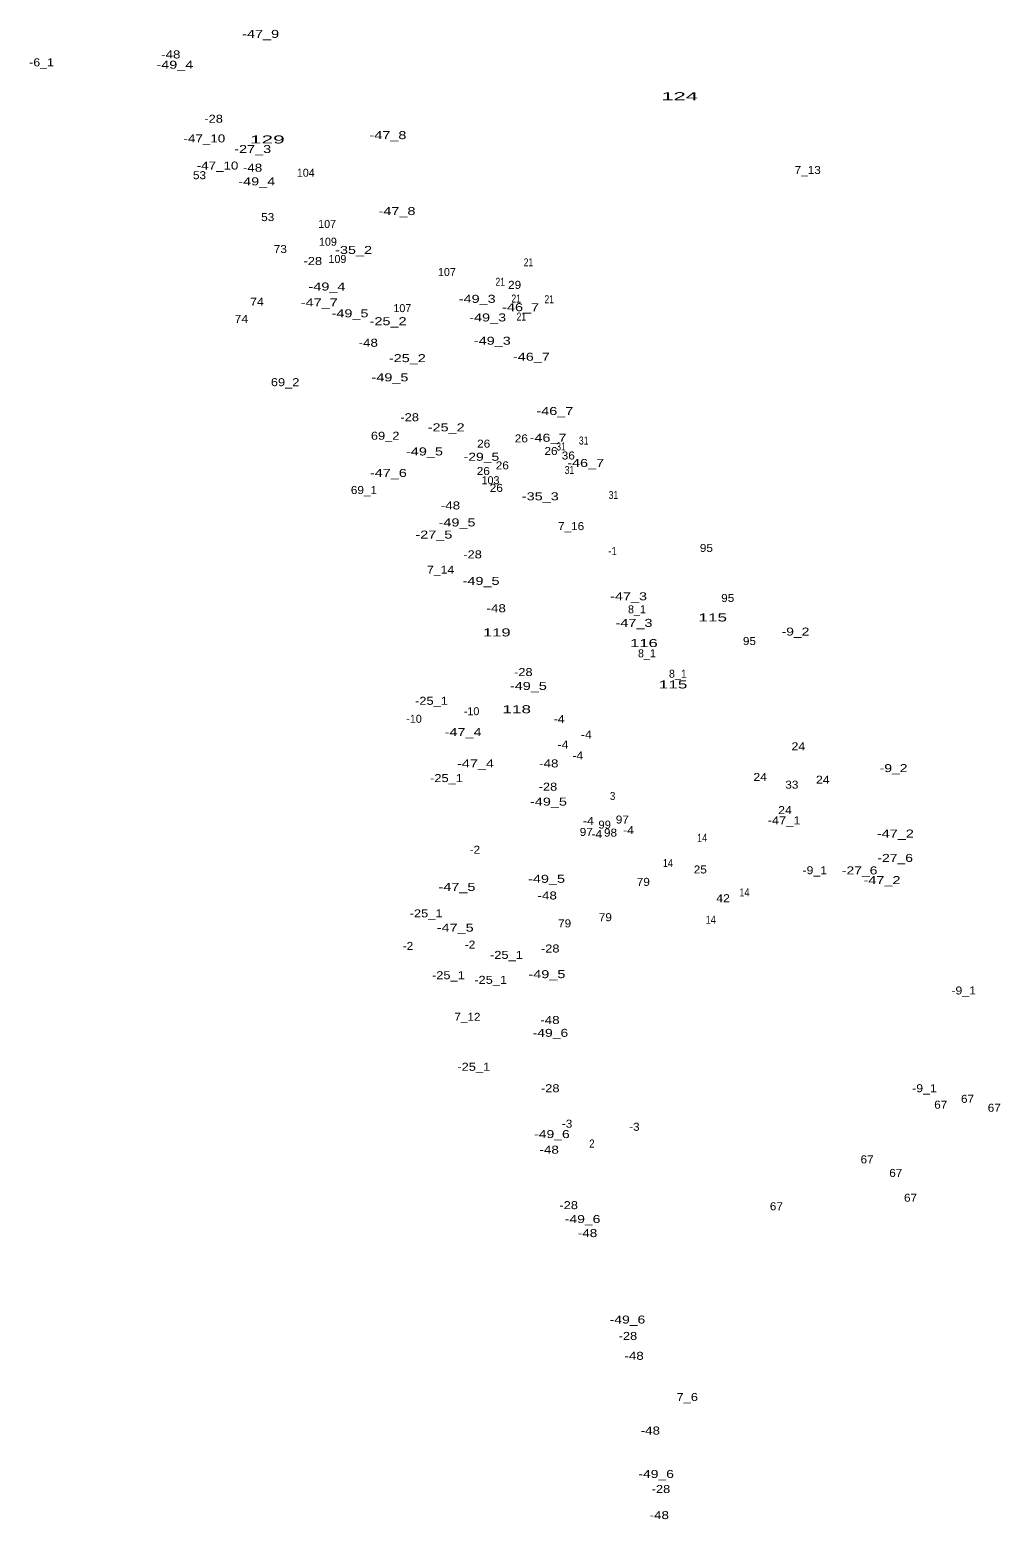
# Model space of a CAD drawing. Extents: x -663705 to -661666, y -1002081 to -999269.
# Drawn here: x -662976 to -662490, y -1002081 to -1001336 of the extents above; entities that cross this region are included whole.
import ezdxf
from ezdxf.enums import TextEntityAlignment as Align

# ---------------------------------------------------------------- set-up
doc = ezdxf.new("R2010")
doc.units = 0
doc.header["$LTSCALE"] = 1.6
doc.layers.add('24', color=7, linetype='Continuous')

msp = doc.modelspace()

# ---------------------------------------------------------------- texts
at = {"layer": '24'}
for s, width, p in [('-47_9', 1.35, (-662860.101, -1001340.27)), ('-6_1', 1.15, (-662969.66, -1001354.49)), ('-49_4', 1.35, (-662903.01, -1001355.68)), ('-48', 1.25, (-662905.05, -1001350.54)), ('124', 2.05, (-662650.563, -1001371.41)), ('-28', 1.2, (-662883.62, -1001382.68)), ('-47_10', 1.25, (-662888.24, -1001392.52)), ('129', 1.95, (-662856.773, -1001393.04)), ('-47_8', 1.35, (-662796.439, -1001390.88)), ('-27_3', 1.35, (-662864.07, -1001397.83)), ('-47_10', 1.25, (-662881.65, -1001406.1)), ('-48', 1.25, (-662864.14, -1001407.17)), ('7_13', 1.1, (-662586.549, -1001408.3)), ('53', 1.1, (-662890.679, -1001410.9)), ('-49_4', 1.35, (-662862.03, -1001414)), ('-47_8', 1.35, (-662791.91, -1001428.85)), ('53', 1.1, (-662856.559, -1001431.85)), ('73', 1.1, (-662850.26, -1001447.81)), ('-35_2', 1.35, (-662813.61, -1001448.28)), ('-28', 1.2, (-662834.02, -1001453.83)), ('21', 0.8, (-662726.179, -1001454.48)), ('-49_4', 1.35, (-662826.939, -1001466.56)), ('21', 0.8, (-662740.309, -1001464.19)), ('29', 1.1, (-662733.11, -1001465.73)), ('74', 1.15, (-662861.94, -1001474.19)), ('-47_7', 1.35, (-662830.791, -1001474.54)), ('-49_3', 1.35, (-662751.82, -1001472.72)), ('21', 0.8, (-662732.329, -1001472.56)), ('21', 0.8, (-662715.799, -1001472.94)), ('74', 1.15, (-662869.7, -1001482.73)), ('-49_5', 1.35, (-662815.41, -1001479.98)), ('-49_3', 1.35, (-662746.58, -1001482.03)), ('-46_7', 1.35, (-662730.091, -1001476.91)), ('21', 0.8, (-662729.74, -1001481.6)), ('-25_2', 1.35, (-662796.36, -1001483.91)), ('-48', 1.25, (-662806.29, -1001494.69)), ('-49_3', 1.35, (-662744.26, -1001493.67)), ('-25_2', 1.35, (-662786.75, -1001502.38)), ('-46_7', 1.35, (-662724.711, -1001501.67)), ('-49_5', 1.35, (-662795.44, -1001511.98)), ('69_2', 1.2, (-662847.86, -1001514.4)), ('-28', 1.2, (-662785.58, -1001531.91)), ('-46_7', 1.35, (-662712.981, -1001528.8)), ('69_2', 1.2, (-662797.84, -1001541.17)), ('-25_2', 1.35, (-662767.329, -1001536.99)), ('26', 1.1, (-662729.76, -1001542.51)), ('-46_7', 1.35, (-662716.38, -1001542.18)), ('-49_5', 1.35, (-662778.18, -1001549.02)), ('26', 1.1, (-662748.57, -1001545.13)), ('26', 1.1, (-662714.93, -1001548.81)), ('31', 0.8, (-662709.89, -1001546.54)), ('31', 0.8, (-662698.569, -1001543.58)), ('-29_5', 1.3, (-662749.71, -1001551.69)), ('26', 1.1, (-662739.26, -1001555.99)), ('36', 1.1, (-662706.28, -1001551.06)), ('-46_7', 1.35, (-662697.571, -1001554.78)), ('-47_6', 1.35, (-662796.24, -1001559.78)), ('26', 1.1, (-662748.77, -1001558.8)), ('31', 0.8, (-662705.669, -1001558.29)), ('69_1', 1.1, (-662808.461, -1001568.33)), ('26', 1.1, (-662742.27, -1001567.24)), ('-35_3', 1.35, (-662720.27, -1001571.46)), ('31', 0.8, (-662683.669, -1001570.8)), ('-48', 1.25, (-662765.19, -1001576.03)), ('-49_5', 1.35, (-662761.9, -1001584.51)), ('7_16', 1.1, (-662704.87, -1001586.37)), ('-27_5', 1.35, (-662773.49, -1001590.6)), ('-28', 1.2, (-662754.13, -1001600.49)), ('-1', 0.9, (-662684.101, -1001598.82)), ('95', 1.1, (-662637.21, -1001597.27)), ('7_14', 1.15, (-662770.1, -1001608.14)), ('-49_5', 1.35, (-662749.88, -1001613.75)), ('-47_3', 1.35, (-662676.11, -1001621.45)), ('95', 1.1, (-662626.54, -1001622.29)), ('-48', 1.25, (-662742.31, -1001627.41)), ('115', 1.6, (-662634.034, -1001632.03)), ('119', 1.55, (-662742.029, -1001639.5)), ('-47_3', 1.35, (-662673.4, -1001634.74)), ('-9_2', 1.3, (-662592.66, -1001639.08)), ('116', 1.55, (-662668.439, -1001644.83)), ('95', 1.1, (-662615.68, -1001643.81)), ('-28', 1.2, (-662728.75, -1001659.33)), ('-49_5', 1.35, (-662726.23, -1001666.27)), ('115', 1.6, (-662653.864, -1001665.52)), ('-25_1', 1.2, (-662774.679, -1001673.7)), ('118', 1.6, (-662732.064, -1001677.9)), ('-4', 1.15, (-662710.84, -1001682.81)), ('-47_4', 1.35, (-662758.87, -1001689.33)), ('-4', 1.15, (-662697.27, -1001690.57)), ('-4', 1.15, (-662708.9, -1001695.61)), ('24', 1.15, (-662591.22, -1001696.45)), ('-47_4', 1.35, (-662752.669, -1001705.04)), ('-48', 1.25, (-662716.02, -1001705.01)), ('-4', 1.15, (-662701.53, -1001701.04)), ('-25_1', 1.2, (-662767.179, -1001712.35)), ('24', 1.15, (-662610.309, -1001711.77)), ('24', 1.15, (-662579, -1001713.13)), ('-9_2', 1.3, (-662543.61, -1001707.35)), ('-28', 1.2, (-662716.45, -1001716.64)), ('3', 0.9, (-662684.09, -1001721.28)), ('33', 1.1, (-662594.49, -1001715.62)), ('-49_5', 1.35, (-662716.18, -1001724.1)), ('24', 1.15, (-662597.91, -1001728.35)), ('-4', 1.15, (-662696.2, -1001733.72)), ('99', 1.05, (-662688.08, -1001735.61)), ('97', 1.1, (-662679.25, -1001733.06)), ('-47_1', 1.2, (-662598.35, -1001733.48)), ('97', 1.1, (-662697.28, -1001739.27)), ('-4', 1.15, (-662692.03, -1001740.29)), ('98', 1.1, (-662685.15, -1001739.61)), ('-4', 1.15, (-662676.14, -1001738.35)), ('14', 0.85, (-662639.35, -1001742.2)), ('-47_2', 1.35, (-662542.709, -1001740.07)), ('-2', 1.1, (-662752.97, -1001748.16)), ('14', 0.85, (-662656.459, -1001754.79)), ('25', 1.1, (-662640.26, -1001758.02)), ('-9_1', 1.15, (-662583.01, -1001758.4)), ('-27_6', 1.3, (-662560.581, -1001758.5)), ('-27_6', 1.3, (-662542.801, -1001752.25)), ('-49_5', 1.35, (-662717.15, -1001762.7)), ('79', 1.1, (-662668.74, -1001764.23)), ('-47_2', 1.35, (-662549.4, -1001763.35)), ('-47_5', 1.35, (-662761.939, -1001766.75)), ('-48', 1.25, (-662716.8, -1001771.03)), ('42', 1.15, (-662628.87, -1001772.41)), ('14', 0.85, (-662618.209, -1001769.5)), ('-25_1', 1.2, (-662777.37, -1001779.97)), ('-47_5', 1.35, (-662762.809, -1001787.11)), ('79', 1.1, (-662708.1, -1001784.98)), ('79', 1.1, (-662687.74, -1001781.88)), ('14', 0.85, (-662635.03, -1001783.16)), ('-2', 1.1, (-662786.41, -1001796.25)), ('-2', 1.1, (-662755.39, -1001795.58)), ('-25_1', 1.2, (-662737.189, -1001800.74)), ('-28', 1.2, (-662715.3, -1001797.54)), ('-25_1', 1.2, (-662766.22, -1001810.9)), ('-49_5', 1.35, (-662716.96, -1001810.37)), ('-25_1', 1.2, (-662745.069, -1001813.21)), ('-9_1', 1.15, (-662508.561, -1001818.52)), ('7_12', 1.1, (-662756.73, -1001831.7)), ('-48', 1.25, (-662715.44, -1001833.28)), ('-49_6', 1.3, (-662715.211, -1001839.71)), ('-25_1', 1.2, (-662753.53, -1001856.67)), ('-28', 1.2, (-662715.3, -1001867.4)), ('-9_1', 1.15, (-662528.14, -1001867.39)), ('67', 1.1, (-662520.02, -1001875.61)), ('67', 1.1, (-662506.64, -1001872.7)), ('67', 1.1, (-662493.26, -1001877.16)), ('-3', 1.1, (-662706.87, -1001885.13)), ('-49_6', 1.3, (-662714.441, -1001890.33)), ('-3', 1.1, (-662673.23, -1001886.68)), ('-48', 1.25, (-662715.83, -1001898.13)), ('2', 0.9, (-662694.459, -1001895.04)), ('67', 1.1, (-662556.85, -1001902.95)), ('67', 1.1, (-662542.5, -1001909.74)), ('67', 1.1, (-662535.14, -1001922.15)), ('-28', 1.2, (-662706.07, -1001925.86)), ('67', 1.1, (-662602.22, -1001926.42)), ('-49_6', 1.3, (-662699.12, -1001932.8)), ('-48', 1.25, (-662696.63, -1001939.83)), ('-49_6', 1.3, (-662676.671, -1001983.06)), ('-28', 1.2, (-662676.46, -1001991.24)), ('-48', 1.25, (-662673.37, -1002001.19)), ('7_6', 1.2, (-662646.78, -1002021.78)), ('-48', 1.25, (-662665.23, -1002038.54)), ('-49_6', 1.3, (-662662.331, -1002060.25)), ('-28', 1.2, (-662659.93, -1002067.78)), ('-48', 1.25, (-662660.77, -1002080.82))]:
    msp.add_text(s, height=4, dxfattribs=dict(at, width=width)).set_placement(p, align=Align.CENTER)
for s, p in [('104', (-662837.549, -1001409.68)), ('107', (-662826.861, -1001435.28)), ('109', (-662826.461, -1001444.17)), ('109', (-662821.711, -1001452.8)), ('107', (-662766.951, -1001459.33)), ('107', (-662789.25, -1001477.37)), ('103', (-662745.15, -1001563.41)), ('8_1', (-662671.94, -1001627.95)), ('8_1', (-662666.94, -1001649.97)), ('8_1', (-662651.47, -1001660.16)), ('-10', (-662783.41, -1001682.69)), ('-10', (-662754.62, -1001678.91))]:
    msp.add_text(s, height=4, dxfattribs=at).set_placement(p, align=Align.CENTER)

doc.saveas('drawing.dxf')
